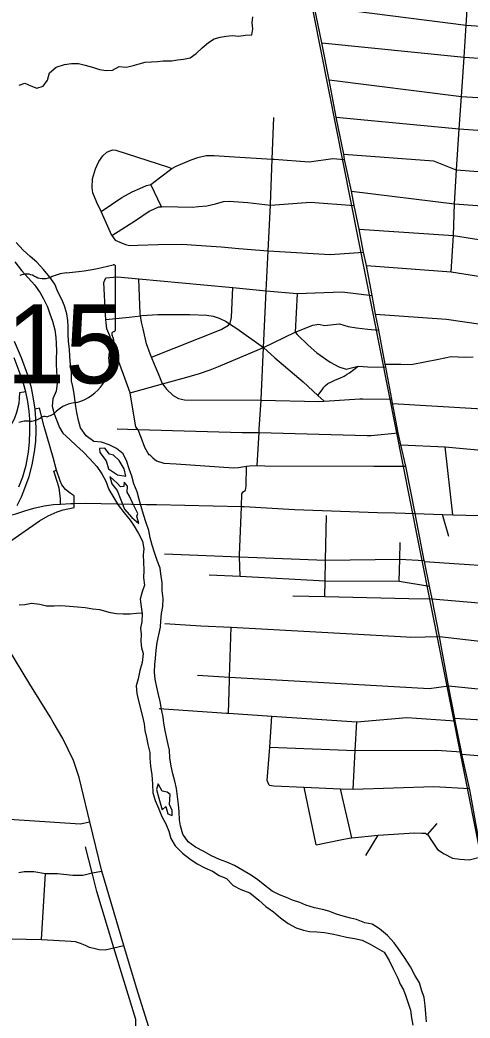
# Model space of a CAD drawing. Extents: x 0 to 34, y 0 to 22.
# Drawn here: x 14.22 to 14.97, y 14.965 to 16.629 of the extents above; entities that cross this region are included whole.
import ezdxf

# ---------------------------------------------------------------- set-up
doc = ezdxf.new("R2010")
doc.units = 0
for name, color, linetype in [('GM_X_City_Street', 7, 'Continuous'), ('GM_X_County_Road', 7, 'Continuous'), ('GM_X_Interchange_Ramps', 7, 'Continuous'), ('GM_X_Major_River', 7, 'Continuous'), ('GM_X_Minor_River', 7, 'Continuous'), ('GM_X_Rail_Line', 7, 'Continuous'), ('GM_X_State_Route', 7, 'Continuous'), ('GM_X_State_Shield', 7, 'Continuous')]:
    doc.layers.add(name, color=color, linetype=linetype)

msp = doc.modelspace()

# ---------------------------------------------------------------- linework, layer by layer
at = {"layer": 'GM_X_City_Street'}
for p, q in [((14.4554, 16.3174), (14.4377, 16.3544)), ((14.9415, 15.8041), (14.9288, 15.9174)), ((14.9345, 15.7678), (14.924, 15.8046)), ((14.7133, 15.2543), (14.6936, 15.3501)), ((14.7731, 15.2659), (14.7541, 15.3476)), ((14.9148, 15.2896), (14.8984, 15.2714)), ((14.2554, 15.0965), (14.2621, 15.2062))]:
    msp.add_line(p, q, dxfattribs=at)
for points in [[(14.9384, 16.2089), (14.9424, 16.2695), (14.9439, 16.3221), (14.9476, 16.379), (14.9521, 16.4473), (14.9557, 16.5008), (14.96, 16.5664), (14.9635, 16.62), (14.9699, 16.7159)], [(14.7101, 16.652), (14.9635, 16.62), (15.1828, 16.6056), (15.184, 16.6056), (15.3582, 16.5949), (15.3776, 16.5937), (15.4965, 16.5864), (15.4973, 16.5864), (15.7101, 16.5716)], [(14.8425, 15.9815), (14.8409, 15.9896), (14.8395, 15.9969), (14.8295, 16.0502), (14.8286, 16.0549), (14.8179, 16.1116), (14.8124, 16.1382), (14.8066, 16.1695), (14.7974, 16.2196), (14.7923, 16.2418), (14.785, 16.28), (14.7768, 16.3192), (14.7722, 16.3434), (14.7607, 16.3963), (14.7596, 16.4051), (14.747, 16.4667), (14.7351, 16.5286), (14.7227, 16.5905), (14.7101, 16.652)], [(14.7227, 16.5905), (14.96, 16.5664), (15.1788, 16.5517), (15.3532, 16.5412), (15.376, 16.5399), (15.3806, 16.5396)], [(14.7351, 16.5286), (14.9557, 16.5008), (15.1741, 16.4876), (15.3471, 16.4758), (15.4844, 16.4665), (15.4853, 16.4665), (15.7027, 16.4521)], [(14.6152, 15.8859), (14.6183, 15.9409), (14.6187, 15.9466), (14.6215, 15.9948), (14.6215, 15.9963), (14.6256, 16.0829), (14.63, 16.1772), (14.6323, 16.2217), (14.6334, 16.2441), (14.6372, 16.3199), (14.6372, 16.3215), (14.6402, 16.3968), (14.643, 16.4661)], [(14.747, 16.4667), (14.9521, 16.4473), (15.1699, 16.4318), (15.1706, 16.4318), (15.3126, 16.4201), (15.4795, 16.4047), (15.6985, 16.3888)], [(14.373, 16.2696), (14.3552, 16.3092), (14.3478, 16.3246), (14.341, 16.3406), (14.3399, 16.3493), (14.3407, 16.3641), (14.3453, 16.3804), (14.351, 16.3929), (14.3579, 16.402), (14.3643, 16.4085), (14.3738, 16.4119)], [(14.3738, 16.4119), (14.3795, 16.4115), (14.467, 16.3831), (14.4726, 16.3813), (14.4798, 16.3851), (14.4904, 16.3893), (14.5049, 16.3957), (14.5159, 16.3995), (14.5299, 16.4029), (14.5435, 16.4028), (14.5685, 16.4013), (14.6402, 16.3968), (14.6435, 16.3966), (14.7017, 16.3924), (14.7413, 16.3979), (14.7607, 16.3963)], [(14.7596, 16.4051), (14.9092, 16.3939), (14.9453, 16.3792), (14.9476, 16.379), (15.1651, 16.3623), (15.2654, 16.3557), (15.4735, 16.3409), (15.6943, 16.3235)], [(14.3552, 16.3092), (14.3895, 16.3329), (14.4066, 16.3424), (14.4195, 16.348), (14.4305, 16.3529), (14.4377, 16.3544), (14.4521, 16.3654), (14.4726, 16.3813)], [(14.7722, 16.3434), (14.9439, 16.3221), (14.9445, 16.3221), (15.1612, 16.3058), (15.2012, 16.3029), (15.3059, 16.2953), (15.4689, 16.2818), (15.6905, 16.2658)], [(14.4462, 16.315), (14.4503, 16.3168), (14.4512, 16.3172), (14.4554, 16.3174), (14.4592, 16.3176), (14.5069, 16.3164), (14.5171, 16.3175), (14.5312, 16.319), (14.5456, 16.3224), (14.5588, 16.3258), (14.5683, 16.3265), (14.5997, 16.3242), (14.6372, 16.3199), (14.7038, 16.3249), (14.7768, 16.3192)], [(14.373, 16.2696), (14.4125, 16.2945), (14.4353, 16.3097), (14.4429, 16.3135), (14.4462, 16.315)], [(14.373, 16.2696), (14.3783, 16.2616), (14.3863, 16.2581), (14.3957, 16.2543), (14.4022, 16.2528), (14.4162, 16.2532), (14.4499, 16.2542), (14.4893, 16.2549), (14.5298, 16.2522), (14.5548, 16.2503), (14.5844, 16.2479), (14.6334, 16.2441), (14.7368, 16.238), (14.7923, 16.2418)], [(14.785, 16.28), (14.9424, 16.2695), (15.1076, 16.2433), (15.1398, 16.2406), (15.1474, 16.2405), (15.1568, 16.2428), (15.1668, 16.2447), (15.1702, 16.2453), (15.1788, 16.2469), (15.1887, 16.2484), (15.2012, 16.2484), (15.2944, 16.2395), (15.3701, 16.2322), (15.4512, 16.2241), (15.4644, 16.2233), (15.4951, 16.2214), (15.5951, 16.2144), (15.6864, 16.2081)], [(14.7974, 16.2196), (14.9384, 16.2089), (15.0514, 16.191), (15.1086, 16.1867), (15.1252, 16.1833), (15.1313, 16.1787), (15.1366, 16.1742), (15.1403, 16.1696), (15.1445, 16.1616), (15.1471, 16.1491)], [(14.3626, 16.199), (14.3823, 16.2005), (14.4176, 16.1972), (14.5259, 16.1873), (14.5743, 16.1826), (14.63, 16.1772), (14.682, 16.1726), (14.7567, 16.1755), (14.8066, 16.1695)], [(14.4409, 15.8987), (14.4349, 15.9051), (14.4349, 15.9032), (14.4277, 15.9162), (14.4217, 15.9329), (14.4168, 15.9454), (14.4164, 15.946), (14.4149, 15.948), (14.413, 15.9507), (14.4033, 16.0065), (14.4031, 16.0073), (14.377, 16.0787), (14.3695, 16.1022), (14.3646, 16.114), (14.3631, 16.1238), (14.3627, 16.1296), (14.362, 16.1375), (14.3595, 16.191), (14.3626, 16.199)], [(14.4572, 16.0224), (14.4504, 16.0391), (14.444, 16.0546), (14.439, 16.0669), (14.4369, 16.0721), (14.4305, 16.0888), (14.4249, 16.1139), (14.4223, 16.1249), (14.4205, 16.1356), (14.42, 16.1389), (14.4176, 16.1972)], [(14.439, 16.0669), (14.5552, 16.1125), (14.5673, 16.1201), (14.5691, 16.1224), (14.57, 16.1235), (14.5723, 16.133), (14.5743, 16.1826)], [(14.682, 16.1726), (14.6783, 16.1081), (14.682, 16.1046), (14.7002, 16.0868), (14.7146, 16.0739), (14.7259, 16.0659), (14.7369, 16.0583), (14.7513, 16.0503), (14.7634, 16.0465), (14.7835, 16.0515)], [(14.3627, 16.1296), (14.4018, 16.1333), (14.4205, 16.1356), (14.4227, 16.1359), (14.4496, 16.1377), (14.503, 16.138), (14.5314, 16.1368), (14.542, 16.1349), (14.5515, 16.1315), (14.5632, 16.1262), (14.5691, 16.1224), (14.581, 16.1147), (14.6256, 16.0829), (14.6445, 16.0653), (14.6917, 16.0254), (14.716, 16.003), (14.7266, 15.9933)], [(14.8124, 16.1382), (14.9306, 16.1298), (15.0757, 16.109), (15.1379, 16.1043), (15.1693, 16.1046), (15.2265, 16.1053), (15.2618, 16.1041), (15.2966, 16.101), (15.2974, 16.101), (15.3504, 16.0975), (15.3799, 16.0937), (15.4547, 16.097), (15.4845, 16.0965), (15.5773, 16.0933), (15.6448, 16.0913), (15.6797, 16.0902)], [(14.4031, 16.0073), (14.4572, 16.0224), (14.4978, 16.0333), (14.519, 16.0397), (14.5368, 16.0454), (14.5505, 16.051), (14.6256, 16.0829), (14.6783, 16.1081), (14.7079, 16.1202), (14.7181, 16.1217), (14.7272, 16.1194), (14.7525, 16.1224), (14.7669, 16.1178), (14.7808, 16.1155), (14.7995, 16.1134), (14.8179, 16.1116)], [(14.8286, 16.0549), (14.8546, 16.0551), (14.8716, 16.0545), (14.9172, 16.0631), (14.9384, 16.0677), (14.9621, 16.0669), (14.9753, 16.0671)], [(14.716, 16.003), (14.7254, 16.0147), (14.7254, 16.0158), (14.7292, 16.0192), (14.733, 16.023), (14.7391, 16.0257), (14.7459, 16.0291), (14.7527, 16.0317), (14.7599, 16.0351), (14.7649, 16.0385), (14.7691, 16.0404), (14.7835, 16.0515), (14.7919, 16.0509), (14.7997, 16.0507), (14.8295, 16.0502)], [(14.4572, 16.0224), (14.464, 16.0136), (14.4749, 16.003), (14.484, 15.998), (14.4939, 15.9954), (14.6215, 15.9948), (14.7181, 15.9927), (14.7266, 15.9933), (14.7863, 15.9974), (14.7914, 15.9973), (14.8395, 15.9969)], [(14.8409, 15.9896), (15.1032, 15.9738), (15.2949, 15.9667), (15.4475, 15.9619), (15.6726, 15.9539)], [(15.0525, 14.9194), (15.041, 14.9798), (15.0256, 15.057), (15.0128, 15.1225), (15.0019, 15.179), (14.9904, 15.2346), (14.9808, 15.2843), (14.9702, 15.3427), (14.969, 15.348), (14.9563, 15.405), (14.9556, 15.4092), (14.9453, 15.4607), (14.9444, 15.4649), (14.9343, 15.5189), (14.9189, 15.6013), (14.9066, 15.6638), (14.9023, 15.6851), (14.8942, 15.7259), (14.8938, 15.7281), (14.8786, 15.8059), (14.8629, 15.8852), (14.8548, 15.9204), (14.8504, 15.9406), (14.8425, 15.9815)], [(14.3816, 15.947), (14.4164, 15.946), (14.5903, 15.9413), (14.6183, 15.9409), (14.7986, 15.9362), (14.8053, 15.936), (14.8504, 15.9406)], [(14.8548, 15.9204), (14.9288, 15.9174), (15.1028, 15.9014), (15.2936, 15.8957), (15.4442, 15.8918), (15.6494, 15.8865), (15.6692, 15.886)], [(14.4409, 15.8987), (14.4474, 15.8937), (14.4595, 15.8903), (14.4803, 15.8891), (14.5758, 15.8821), (14.5841, 15.8829), (14.5975, 15.8848), (14.6023, 15.8855), (14.6152, 15.8859), (14.6281, 15.8858), (14.8095, 15.8853), (14.8629, 15.8852)], [(14.5865, 15.7015), (14.5857, 15.7341), (14.5856, 15.7375), (14.5892, 15.8168), (14.5892, 15.8178), (14.5897, 15.8388), (14.5916, 15.8423), (14.5957, 15.8453), (14.5969, 15.8517), (14.5975, 15.8848)], [(14.0661, 15.7187), (14.1001, 15.7426), (14.1495, 15.7746), (14.1685, 15.7864), (14.1886, 15.7974), (14.206, 15.8038), (14.2129, 15.8057), (14.2276, 15.8106), (14.2425, 15.8152), (14.2602, 15.8191), (14.2754, 15.8209), (14.2871, 15.8217), (14.3042, 15.8226), (14.31, 15.8228)], [(14.31, 15.8228), (14.3291, 15.8233), (14.381, 15.8223), (14.43, 15.8213)], [(14.43, 15.8213), (14.447, 15.821), (14.5892, 15.8178), (14.5933, 15.8177), (14.6772, 15.8127), (14.8155, 15.8081), (14.845, 15.8071), (14.8786, 15.8059)], [(14.7278, 15.6676), (14.7284, 15.6941), (14.7291, 15.7285), (14.7306, 15.8029)], [(14.8786, 15.8059), (14.924, 15.8046), (14.9415, 15.8041), (15.0498, 15.8009), (15.2916, 15.7836), (15.3859, 15.7799), (15.5192, 15.7758), (15.637, 15.7726), (15.6621, 15.772)], [(14.8517, 15.6934), (14.8532, 15.7298), (14.8537, 15.7581)], [(14.4605, 15.739), (14.5857, 15.7341), (14.7291, 15.7285), (14.8532, 15.7298), (14.8938, 15.7281)], [(14.8942, 15.7259), (15.0594, 15.7148), (15.1356, 15.6983), (15.2897, 15.691)], [(14.5352, 15.7042), (14.5865, 15.7015), (14.7284, 15.6941), (14.8517, 15.6934), (14.9023, 15.6851)], [(14.6746, 15.6688), (14.7278, 15.6676), (14.8678, 15.6647), (14.9066, 15.6638)], [(14.9066, 15.6638), (15.0817, 15.649), (15.2875, 15.6235), (15.3556, 15.6206), (15.426, 15.6158), (15.4331, 15.6162), (15.4385, 15.62), (15.4449, 15.6257), (15.4491, 15.6298), (15.4533, 15.6317), (15.4582, 15.6321), (15.462, 15.6268), (15.4748, 15.6089), (15.4777, 15.6035)], [(14.4613, 15.6231), (14.5214, 15.6192), (14.572, 15.6165), (14.864, 15.6006), (14.8714, 15.6002), (14.9189, 15.6013)], [(14.5672, 15.4735), (14.569, 15.5283), (14.5692, 15.5336), (14.572, 15.6165)], [(14.9189, 15.6013), (15.0781, 15.583), (15.2856, 15.5678), (15.354, 15.5628)], [(14.5155, 15.5366), (14.5692, 15.5336), (14.8926, 15.5151), (14.9017, 15.5146), (14.9343, 15.5189)], [(14.9343, 15.5189), (15.2922, 15.4829), (15.2973, 15.4826), (15.3388, 15.4809), (15.3453, 15.482), (15.349, 15.4839)], [(14.4516, 15.4813), (14.5639, 15.4737), (14.5672, 15.4735), (14.6397, 15.4687), (14.7811, 15.4592), (14.8646, 15.4663), (14.9453, 15.4607)], [(14.6353, 15.3534), (14.6319, 15.3614), (14.636, 15.4169), (14.6397, 15.4687)], [(14.7749, 15.3467), (14.7784, 15.4113), (14.7811, 15.4592)], [(14.9444, 15.4649), (15.0703, 15.4571), (15.2038, 15.4394), (15.2929, 15.4343)], [(14.636, 15.4169), (14.7784, 15.4113), (14.9148, 15.4117), (14.9556, 15.4092)], [(14.9563, 15.405), (15.154, 15.3882), (15.165, 15.3878), (15.1688, 15.3882), (15.1715, 15.3886), (15.1749, 15.3912), (15.1756, 15.395), (15.1779, 15.4041), (15.1795, 15.4079), (15.1833, 15.4098), (15.1912, 15.4102), (15.2848, 15.3994), (15.3004, 15.4135)], [(14.6353, 15.3534), (14.6429, 15.3522), (14.6936, 15.3501), (14.7541, 15.3476), (14.7749, 15.3467), (14.9099, 15.3512), (14.969, 15.348)], [(13.8269, 15.3101), (13.8363, 15.3097), (13.9737, 15.3011), (14.159, 15.2994), (14.3198, 15.2889), (14.3359, 15.2921)], [(14.7133, 15.2543), (14.7538, 15.2624), (14.7712, 15.2657), (14.7731, 15.2659), (14.8169, 15.2704), (14.8772, 15.2742), (14.8897, 15.2733), (14.8957, 15.2733), (14.8984, 15.2714), (14.8995, 15.2706), (14.9059, 15.2611), (14.916, 15.2462), (14.9269, 15.2389), (14.9408, 15.232), (14.9529, 15.2304), (14.9688, 15.2292), (14.9904, 15.2346)], [(14.7964, 15.236), (14.8076, 15.2548), (14.8169, 15.2704)], [(14.4124, 14.9266), (14.4126, 14.9627), (14.3759, 15.0826), (14.348, 15.1761), (14.3401, 15.2071), (14.329, 15.2506)], [(14.2177, 15.2079), (14.2265, 15.2095), (14.2426, 15.2095), (14.2621, 15.2062), (14.282, 15.2065), (14.308, 15.2037), (14.3245, 15.2037), (14.3401, 15.2071), (14.3559, 15.2103)], [(14.1355, 15.0988), (14.2297, 15.0971), (14.2554, 15.0965), (14.3048, 15.0936), (14.3115, 15.0931), (14.3201, 15.0902), (14.3282, 15.0868), (14.3352, 15.0835), (14.343, 15.0816), (14.3518, 15.0794), (14.3616, 15.0791), (14.3759, 15.0826), (14.3927, 15.0864)]]:
    msp.add_lwpolyline(points, dxfattribs=at)
at = {"layer": 'GM_X_County_Road'}
msp.add_line((14.3359, 15.2921), (14.3221, 15.3499), dxfattribs=at)
for points in [[(14.2697, 15.4672), (14.2361, 15.5216), (14.1749, 15.6215), (14.1394, 15.6789), (14.1229, 15.7042), (14.1171, 15.7132)], [(14.3221, 15.3499), (14.3182, 15.3663), (14.3128, 15.3828), (14.3086, 15.3943), (14.2909, 15.4315), (14.2749, 15.4587), (14.2697, 15.4672)], [(14.4924, 14.7526), (14.4342, 14.95), (14.4139, 15.0157), (14.3927, 15.0864), (14.3559, 15.2103), (14.3359, 15.2921)]]:
    msp.add_lwpolyline(points, dxfattribs=at)
at = {"layer": 'GM_X_Interchange_Ramps'}
for points in [[(14.2294, 16.0089), (14.2189, 16.007), (14.2178, 15.9896), (14.214, 15.9747), (14.2098, 15.9635), (14.204, 15.9521), (14.1975, 15.9427), (14.1886, 15.9318), (14.1798, 15.9233), (14.1691, 15.9158), (14.1574, 15.9108), (14.1452, 15.9052), (14.1362, 15.9018)], [(14.31, 15.8228), (14.31, 15.8354), (14.3031, 15.84), (14.2957, 15.8459), (14.2893, 15.8539), (14.2865, 15.8606), (14.2806, 15.8782), (14.275, 15.8993), (14.26, 15.9511), (14.2522, 15.9818), (14.245, 15.9801)], [(14.2871, 15.8217), (14.2871, 15.8308), (14.2862, 15.8398), (14.2851, 15.8484), (14.2827, 15.8564), (14.2761, 15.8767), (14.2806, 15.8782)], [(13.7906, 15.4051), (13.7949, 15.4051), (13.8107, 15.4571), (13.8207, 15.4805), (13.8318, 15.4997), (13.8543, 15.5309), (13.8704, 15.5458), (13.8902, 15.5593), (13.9006, 15.5663), (13.9088, 15.5712), (13.9595, 15.6016), (13.9748, 15.6099), (14.0197, 15.6382), (14.049, 15.6582), (14.1229, 15.7042), (14.2521, 15.7941), (14.2668, 15.8025), (14.2815, 15.8092), (14.2919, 15.8125), (14.3101, 15.8161), (14.31, 15.8228)]]:
    msp.add_lwpolyline(points, dxfattribs=at)
at = {"layer": 'GM_X_Major_River'}
for points in [[(14.3682, 15.9208), (14.3554, 15.9248), (14.3425, 15.9259), (14.3302, 15.9356), (14.3206, 15.9491), (14.3171, 15.9613), (14.3143, 15.9746), (14.3126, 15.9845), (14.311, 15.9967), (14.31, 16.0062), (14.308, 16.018), (14.3055, 16.0275), (14.3054, 16.0412), (14.3038, 16.0538), (14.3029, 16.0675), (14.302, 16.08), (14.3004, 16.0926), (14.3002, 16.1043), (14.3001, 16.1176), (14.2992, 16.1275), (14.2979, 16.1389), (14.2936, 16.1523), (14.2893, 16.1626), (14.2827, 16.1757), (14.278, 16.1883), (14.2695, 16.2002), (14.2588, 16.2129), (14.248, 16.2249), (14.2365, 16.2346), (14.2249, 16.2447), (14.2131, 16.2575)], [(14.2109, 16.2253), (14.2224, 16.211), (14.2331, 16.199), (14.2446, 16.1866), (14.2535, 16.1736), (14.259, 16.164), (14.2655, 16.1506), (14.2694, 16.1391), (14.2738, 16.1269), (14.278, 16.112), (14.2793, 16.0994), (14.2798, 16.0895), (14.2803, 16.0766), (14.2797, 16.0637), (14.2799, 16.0542), (14.2804, 16.0447), (14.281, 16.0345), (14.2819, 16.0227), (14.2797, 16.0098), (14.2746, 15.997), (14.2732, 15.9849), (14.2767, 15.9723), (14.2807, 15.962), (14.2857, 15.9497), (14.2909, 15.9401), (14.3028, 15.9293), (14.3136, 15.9188), (14.3251, 15.9087)], [(14.8975, 14.9589), (14.8963, 14.9722), (14.8954, 14.9863), (14.8934, 14.9996), (14.8891, 15.0126), (14.8855, 15.024), (14.8782, 15.0367), (14.8705, 15.0509), (14.8621, 15.0647), (14.8536, 15.077), (14.8437, 15.0905), (14.8322, 15.1029), (14.8191, 15.1141), (14.8068, 15.122), (14.7947, 15.1241), (14.7808, 15.1297), (14.7709, 15.1318), (14.7585, 15.1354), (14.7472, 15.1387), (14.7348, 15.1435), (14.7238, 15.146), (14.7106, 15.1489), (14.6963, 15.1534), (14.6865, 15.1577), (14.6741, 15.1621), (14.664, 15.1661), (14.6523, 15.1709), (14.6399, 15.1768), (14.6272, 15.187), (14.6142, 15.1971), (14.6029, 15.2045), (14.5906, 15.2116), (14.5775, 15.2198), (14.5647, 15.225), (14.5523, 15.2298), (14.5391, 15.2357), (14.526, 15.2428), (14.5121, 15.2503), (14.5001, 15.2589), (14.4913, 15.272), (14.4874, 15.2857), (14.4857, 15.2956), (14.4849, 15.3093), (14.484, 15.3211), (14.4823, 15.3348), (14.4807, 15.3477), (14.4779, 15.3603), (14.4747, 15.3725), (14.4716, 15.3851), (14.4696, 15.3988), (14.4687, 15.4117), (14.4666, 15.4213), (14.4646, 15.4315), (14.4618, 15.4445), (14.4594, 15.4567), (14.4581, 15.4666), (14.4557, 15.4799), (14.4533, 15.4929), (14.4505, 15.5047), (14.4477, 15.5169), (14.4449, 15.5299), (14.444, 15.5416), (14.4446, 15.5545), (14.4456, 15.5644), (14.4466, 15.5784), (14.4484, 15.5913), (14.4509, 15.6041), (14.4538, 15.6166), (14.4544, 15.6265), (14.4554, 15.6393), (14.458, 15.6514), (14.4586, 15.6643), (14.4566, 15.678), (14.4568, 15.6906), (14.4545, 15.7054), (14.4532, 15.7153), (14.4485, 15.7279), (14.4438, 15.7409), (14.4399, 15.7535), (14.4367, 15.7657), (14.4343, 15.7779), (14.4297, 15.7924), (14.4258, 15.8047), (14.4219, 15.8176), (14.4183, 15.8295), (14.4148, 15.8425), (14.4097, 15.8558), (14.4062, 15.8681), (14.4019, 15.8807), (14.398, 15.8929), (14.3918, 15.9055), (14.3806, 15.9145), (14.3682, 15.9208)], [(14.3251, 15.9087), (14.3359, 15.8971), (14.3478, 15.8844), (14.3562, 15.8724), (14.3628, 15.8602), (14.3678, 15.8464), (14.3763, 15.8322), (14.384, 15.8195), (14.3932, 15.8072), (14.4036, 15.7948), (14.4102, 15.7852), (14.4175, 15.7726), (14.4241, 15.7599), (14.4261, 15.7473), (14.4252, 15.7375), (14.4257, 15.725), (14.4262, 15.7117), (14.4255, 15.6988), (14.4272, 15.687), (14.4236, 15.6756), (14.4199, 15.6636), (14.4219, 15.6506), (14.4236, 15.6392), (14.423, 15.6259), (14.4208, 15.615), (14.4218, 15.6051), (14.4212, 15.5929), (14.4225, 15.5823), (14.4249, 15.5728), (14.4235, 15.5576), (14.4194, 15.5448), (14.4165, 15.5308), (14.4136, 15.5191), (14.4145, 15.5062), (14.4166, 15.4962), (14.4236, 15.4703), (14.4267, 15.4558), (14.428, 15.4444), (14.4308, 15.433), (14.4329, 15.4215), (14.436, 15.4078), (14.4362, 15.3983), (14.4375, 15.385), (14.4394, 15.3705), (14.4407, 15.355), (14.4411, 15.3409), (14.445, 15.3279), (14.4505, 15.3153), (14.4563, 15.3015), (14.4628, 15.2892), (14.4679, 15.2766), (14.4714, 15.2644), (14.4784, 15.2525), (14.4907, 15.2401), (14.503, 15.2308), (14.5153, 15.2225), (14.5281, 15.2155), (14.5405, 15.2099), (14.5517, 15.2032), (14.5641, 15.1977), (14.5753, 15.1865), (14.588, 15.1798), (14.6027, 15.1738), (14.6176, 15.1617), (14.6295, 15.1512), (14.6423, 15.1423), (14.6542, 15.1325), (14.6669, 15.1232), (14.68, 15.1157), (14.6921, 15.1117), (14.7026, 15.1096), (14.7148, 15.109), (14.7276, 15.108), (14.7397, 15.1058), (14.7503, 15.1033), (14.7642, 15.1), (14.7775, 15.0979), (14.7899, 15.0954), (14.8034, 15.0886), (14.8154, 15.082), (14.827, 15.0749), (14.8351, 15.0615), (14.842, 15.0473), (14.8497, 15.0319), (14.8537, 15.022), (14.8588, 15.0124), (14.8627, 15.0017), (14.8674, 14.9887), (14.8706, 14.9788), (14.8726, 14.9658), (14.8747, 14.9536)], [(14.3963, 15.8686), (14.3932, 15.8808), (14.3851, 15.8947), (14.3758, 15.9036), (14.369, 15.9052), (14.3613, 15.9149), (14.3525, 15.9147)], [(14.3525, 15.9147), (14.3528, 15.9078), (14.3631, 15.8939), (14.3674, 15.8806), (14.3824, 15.8708), (14.3963, 15.8686)], [(14.3694, 15.868), (14.3726, 15.8554), (14.3818, 15.8446), (14.3876, 15.8289), (14.3937, 15.8136), (14.4063, 15.7993), (14.4179, 15.7896)], [(14.4179, 15.7896), (14.4147, 15.8018), (14.4163, 15.806), (14.4076, 15.8229), (14.4025, 15.8351), (14.3981, 15.8416), (14.399, 15.8519), (14.3935, 15.8581), (14.3926, 15.8512), (14.3873, 15.8506), (14.3817, 15.8568), (14.3694, 15.868)], [(14.4498, 15.3559), (14.4473, 15.3465), (14.4512, 15.332), (14.4565, 15.3121), (14.4627, 15.3177), (14.4662, 15.3059), (14.4734, 15.3031)], [(14.4734, 15.3031), (14.4735, 15.311), (14.4692, 15.321), (14.4699, 15.3381), (14.465, 15.3419), (14.4567, 15.3436), (14.4498, 15.3559)]]:
    msp.add_lwpolyline(points, dxfattribs=at)
at = {"layer": 'GM_X_Minor_River'}
for points in [[(14.2183, 16.5201), (14.2279, 16.523), (14.2377, 16.5187), (14.2478, 16.5151), (14.2581, 16.518), (14.2658, 16.5285), (14.2686, 16.5402), (14.2798, 16.55), (14.2939, 16.5543), (14.3056, 16.556), (14.3174, 16.5559), (14.3283, 16.5534), (14.3408, 16.5498), (14.3525, 16.5462), (14.3631, 16.5445), (14.3741, 16.5448), (14.3852, 16.551), (14.3965, 16.5497), (14.4068, 16.5519), (14.4182, 16.5555), (14.4281, 16.558), (14.4387, 16.5586), (14.4489, 16.5592), (14.4584, 16.5602), (14.4728, 16.5604), (14.4823, 16.5621), (14.4922, 16.5635), (14.5036, 16.5656), (14.5132, 16.5727), (14.5232, 16.5824), (14.5339, 16.591), (14.5435, 16.5973), (14.5534, 16.5999), (14.5636, 16.6016), (14.5735, 16.6026), (14.5848, 16.6013), (14.5951, 16.6034), (14.6061, 16.6036), (14.6081, 16.6139), (14.6067, 16.6238), (14.608, 16.634)], [(14.4235, 15.64), (14.4138, 15.6395), (14.4036, 15.6382), (14.3918, 15.6383), (14.3805, 15.6389), (14.3707, 15.6409), (14.3529, 15.6454), (14.3412, 15.6467), (14.3283, 15.6488), (14.3154, 15.6501), (14.3022, 15.6511), (14.2878, 15.6524), (14.2764, 15.6518), (14.2639, 15.652), (14.253, 15.6544), (14.2386, 15.6562), (14.2276, 15.6541), (14.2181, 15.6534)]]:
    msp.add_lwpolyline(points, dxfattribs=at)
at = {"layer": 'GM_X_Rail_Line'}
msp.add_lwpolyline([(15.0629, 14.86), (14.8834, 15.7612), (14.6847, 16.7649), (14.6527, 16.9102), (14.6435, 16.9683), (14.6913, 17.888), (14.7271, 18.6816), (14.7867, 19.7867), (14.8027, 20.0965)], dxfattribs=at)
at = {"layer": 'GM_X_State_Route'}
for points in [[(14.215, 15.8193), (14.2224, 15.8338), (14.2279, 15.8481), (14.2347, 15.8678), (14.2402, 15.8873), (14.2441, 15.909), (14.2459, 15.9264), (14.2465, 15.9435), (14.2463, 15.9639), (14.245, 15.9801), (14.2424, 15.9974), (14.2389, 16.0154), (14.2327, 16.0367), (14.222, 16.0654), (14.2104, 16.0926)], [(14.2178, 15.8506), (14.2244, 15.867), (14.2299, 15.8866), (14.2338, 15.9083), (14.2356, 15.9256), (14.2362, 15.9427), (14.236, 15.9631), (14.2349, 15.9765), (14.2325, 15.9927), (14.2294, 16.0089), (14.2257, 16.023), (14.2202, 16.0388), (14.2099, 16.0655)]]:
    msp.add_lwpolyline(points, dxfattribs=at)
at = {"layer": 'GM_X_State_Shield'}
for q in [(14.3791, 16.2174), (14.3791, 16.1127)]:
    msp.add_line((14.3791, 16.1127), q, dxfattribs=at)
for centre, major_axis, start_param, end_param in [((14.2617, 16.4853), (0.3495, 0), 4.814394, 5.042369), ((14.3754, 16.2178), (0.00367, 0), 6.141152, 7.989035), ((14.2304, 16.1873), (0.0222, 0), 0.950623, 2.079405), ((14.2591, 16.2191), (0.0267, 0), 4.081561, 5.145723), ((14.3063, 16.1513), (0.0703, 0), 1.699011, 2.107814), ((14.3782, 16.105), (0.00568, 0), 1.883978, 3.671073), ((14.3421, 16.0918), (0.0341, 0), 5.934695, 6.695948), ((14.3752, 16.1123), (0.00393, 0), 5.05454, 6.418171), ((14.2813, 16.0556), (0.0874, 0), 5.101752, 6.440018), ((14.3922, 16.0689), (0.0248, 0), 2.387724, 3.262537), ((14.3181, 15.9527), (0.0479, 0), 1.647645, 2.488434), ((14.2365, 15.9814), (0.0267, 0), 4.691044, 5.507374), ((14.2607, 15.962), (0.00752, 0), 1.147584, 2.315152), ((14.2575, 15.9895), (0.0282, 0), 4.937069, 5.64225), ((14.2329, 15.9272), (0.0412, 0), 1.495662, 1.94098)]:
    msp.add_ellipse(centre, major_axis=major_axis, ratio=0.8, start_param=start_param, end_param=end_param, dxfattribs=at)

# ---------------------------------------------------------------- texts
msp.add_text('315', height=0.13184, dxfattribs=at).set_placement((14.0986, 16.023))

doc.saveas('drawing.dxf')
